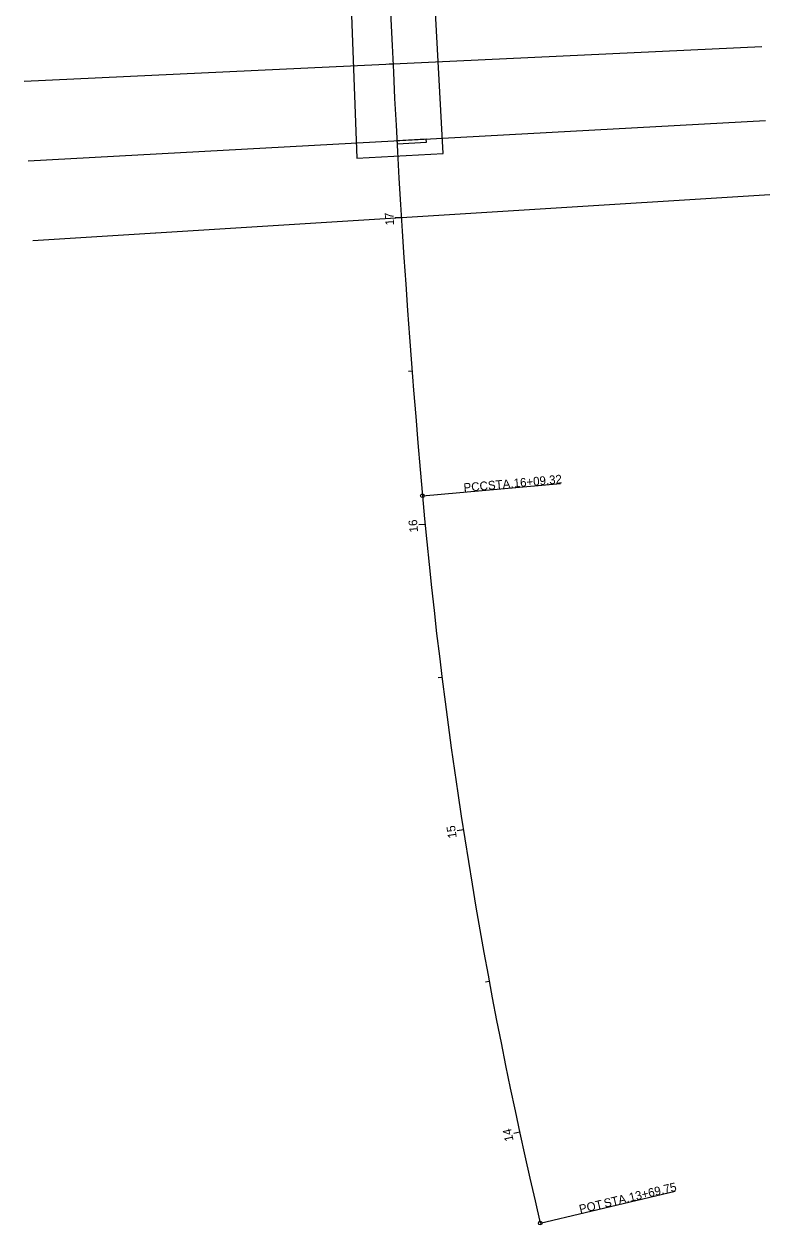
# Model space of a CAD drawing. Extents: x 2283072 to 2287933, y 586198 to 587702.
# Drawn here: x 2284318.2 to 2284560.6, y 586560.4 to 586950.6 of the extents above; entities that cross this region are included whole.
import ezdxf

# ---------------------------------------------------------------- set-up
doc = ezdxf.new("R2010")
doc.units = 0
for name, color, linetype in [('DR_X_Headwall', 7, 'Continuous'), ('DT_X_Void', 7, 'Continuous'), ('PV_X_EOP', 7, 'Continuous'), ('RS_Raster1', 7, 'Continuous'), ('SV_X_Random_Point', 7, 'Continuous'), ('UT_X_Electric_Cells', 7, 'Continuous')]:
    doc.layers.add(name, color=color, linetype=linetype)

msp = doc.modelspace()

# ---------------------------------------------------------------- linework, layer by layer
at = {"layer": 'DR_X_Headwall'}
msp.add_line((2284426.3, 586906.97), (2284454.41, 586908.51), dxfattribs=at)
for points in [[(2284454.41, 586908.51), (2284448.73, 587012.28), (2284463.26, 587034.38)], [(2284402.35, 587013.4), (2284402.35, 587013.4), (2284415.5, 586986.74), (2284424.27, 586962.29), (2284426.3, 586906.97)]]:
    msp.add_lwpolyline(points, dxfattribs=at)
at = {"layer": 'DT_X_Void'}
for p, q in [((2284318.2, 586932), (2284557.94, 586943.31)), ((2284319.52, 586906.14), (2284559.16, 586919.24)), ((2284321.03, 586880.28), (2284560.57, 586895.19))]:
    msp.add_line(p, q, dxfattribs=at)
at = {"layer": 'PV_X_EOP'}
for p, q in [((2284447.66, 586797.32), (2284492.49, 586801.33)), ((2284485.94, 586561.03), (2284529.73, 586571.36))]:
    msp.add_line(p, q, dxfattribs=at)
for centre in [(2284447.66, 586797.32), (2284485.94, 586561.03)]:
    msp.add_circle(centre, 0.6, dxfattribs=at)
at = {"layer": 'RS_Raster1'}
for p, q in [((2284438.07, 586937.66), (2284436.87, 586937.6)), ((2284440.8, 586887.73), (2284438.81, 586887.61)), ((2284444.28, 586837.85), (2284443.09, 586837.76)), ((2284448.52, 586788.04), (2284446.53, 586787.85)), ((2284454, 586738.34), (2284452.81, 586738.19)), ((2284460.95, 586688.83), (2284458.97, 586688.52)), ((2284469.37, 586639.54), (2284468.19, 586639.32)), ((2284479.25, 586590.53), (2284477.3, 586590.1))]:
    msp.add_line(p, q, dxfattribs=at)
at = {"layer": 'SV_X_Random_Point'}
for centre, radius, start, end in [((2287766.93, 587094.71), 3332.56, 180.37508, 185.11985), ((2287766.93, 587094.71), 3332.56, 180.37508, 185.11985), ((2286123.01, 586947.42), 1682.06, 185.11983, 193.28026), ((2286123.01, 586947.42), 1682.06, 185.11983, 193.28026)]:
    msp.add_arc(centre, radius, start, end, dxfattribs=at)
at = {"layer": 'UT_X_Electric_Cells'}
msp.add_lwpolyline([(2284439.34, 586912.69), (2284439.4, 586911.69), (2284448.94, 586912.21), (2284448.9, 586913.21)], close=True, dxfattribs=at)

# ---------------------------------------------------------------- texts
at = {"layer": 'PV_X_EOP'}
for s, rotation, p in [('PCC', 5.1198, (2284461.15, 586798.57)), (' STA. ', 5.1198, (2284468.01, 586799.18)), ('16+09.32', 5.1198, (2284477.42, 586800.02)), ('13+69.75', 13.2803, (2284515.14, 586567.96)), ('POT', 13.2803, (2284498.93, 586564.14)), (' STA. ', 13.2803, (2284505.94, 586565.79))]:
    msp.add_text(s, height=2.8, rotation=rotation, dxfattribs=at).set_placement(p)
at = {"layer": 'RS_Raster1'}
for s, rotation, p in [('17', 93.5608, (2284438.45, 586885.28)), ('16', 95.4373, (2284446.25, 586785.57)), ('15', 98.8436, (2284458.82, 586686.28)), ('14', 102.2499, (2284477.27, 586587.89))]:
    msp.add_text(s, height=2.8, rotation=rotation, dxfattribs=at).set_placement(p)

doc.saveas('drawing.dxf')
